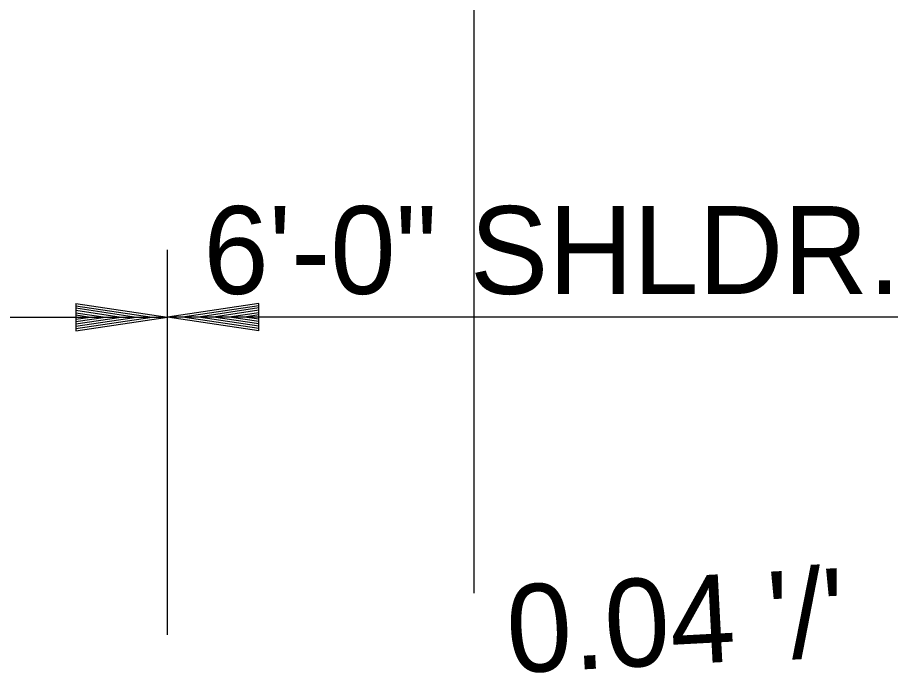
# Model space of a CAD drawing. Extents: x 1364961 to 1365294, y 367927 to 368034.
# Drawn here: x 1365025.01 to 1365030.74, y 367999.87 to 368004.17 of the extents above; entities that cross this region are included whole.
import ezdxf

# ---------------------------------------------------------------- set-up
doc = ezdxf.new("R2010")
doc.units = 0
doc.layers.add('Default', color=7, linetype='Continuous')

msp = doc.modelspace()

# ---------------------------------------------------------------- linework, layer by layer
at = {"layer": 'Default'}
for p, q in [((1365028.0053, 368000.3974), (1365028.0053, 368013.9558)), ((1365025.9943, 368000.1227), (1365025.9943, 368002.6489)), ((1365025.3943, 368002.2969), (1365025.9943, 368002.2069)), ((1365025.3943, 368002.2969), (1365025.3943, 368002.1169)), ((1365025.3943, 368002.2819), (1365025.8943, 368002.2069)), ((1365026.5943, 368002.2969), (1365025.9943, 368002.2069)), ((1365026.5943, 368002.2969), (1365025.9943, 368002.2069)), ((1365026.5943, 368002.2819), (1365026.0943, 368002.2069)), ((1365026.5943, 368002.2819), (1365026.0943, 368002.2069)), ((1365026.5943, 368002.1169), (1365026.5943, 368002.2969)), ((1365026.5943, 368002.1169), (1365026.5943, 368002.2969)), ((1365025.3943, 368002.2669), (1365025.7913, 368002.2069)), ((1365025.3943, 368002.2519), (1365025.6913, 368002.2069)), ((1365025.3943, 368002.2359), (1365025.5893, 368002.2069)), ((1365025.3943, 368002.2209), (1365025.4893, 368002.2069)), ((1365026.5943, 368002.2669), (1365026.1973, 368002.2069)), ((1365026.5943, 368002.2669), (1365026.1973, 368002.2069)), ((1365026.5943, 368002.2519), (1365026.2973, 368002.2069)), ((1365026.5943, 368002.2519), (1365026.2973, 368002.2069)), ((1365026.5943, 368002.2359), (1365026.3993, 368002.2069)), ((1365026.5943, 368002.2359), (1365026.3993, 368002.2069)), ((1365026.5943, 368002.2209), (1365026.4993, 368002.2069)), ((1365026.5943, 368002.2209), (1365026.4993, 368002.2069)), ((1365013.9943, 368002.2069), (1365025.9943, 368002.2069)), ((1365025.3943, 368002.1169), (1365025.9943, 368002.2069)), ((1365025.3943, 368002.1779), (1365025.5893, 368002.2069)), ((1365025.3943, 368002.1469), (1365025.7913, 368002.2069)), ((1365025.3943, 368002.1319), (1365025.8943, 368002.2069)), ((1365025.3943, 368002.1619), (1365025.6913, 368002.2069)), ((1365025.3943, 368002.1929), (1365025.4893, 368002.2069)), ((1365026.5943, 368002.1169), (1365025.9943, 368002.2069)), ((1365026.5943, 368002.1169), (1365025.9943, 368002.2069)), ((1365031.9943, 368002.2069), (1365025.9943, 368002.2069)), ((1365026.5943, 368002.1319), (1365026.0943, 368002.2069)), ((1365026.5943, 368002.1319), (1365026.0943, 368002.2069)), ((1365026.5943, 368002.1469), (1365026.1973, 368002.2069)), ((1365026.5943, 368002.1469), (1365026.1973, 368002.2069)), ((1365026.5943, 368002.1619), (1365026.2973, 368002.2069)), ((1365026.5943, 368002.1619), (1365026.2973, 368002.2069)), ((1365026.5943, 368002.1779), (1365026.3993, 368002.2069)), ((1365026.5943, 368002.1779), (1365026.3993, 368002.2069)), ((1365026.5943, 368002.1929), (1365026.4993, 368002.2069)), ((1365026.5943, 368002.1929), (1365026.4993, 368002.2069))]:
    msp.add_line(p, q, dxfattribs=at)

# ---------------------------------------------------------------- texts
msp.add_text('6\'-0" SHLDR.', height=0.576, dxfattribs=at).set_placement((1365026.2304, 368002.3589))
msp.add_text("0.04 '/'", height=0.576, rotation=3, dxfattribs=at).set_placement((1365028.2329, 367999.8711))

doc.saveas('drawing.dxf')
